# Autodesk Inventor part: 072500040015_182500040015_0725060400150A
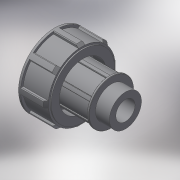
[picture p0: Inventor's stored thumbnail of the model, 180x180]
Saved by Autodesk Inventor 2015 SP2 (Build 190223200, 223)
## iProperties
Created: 2017-04
Part Number: 072500040015_182500040015_0725060400150A
Material: Generic
Description: PLASSON THREADED ADAPTOR 40-1.1/2"
Document SubType Name: Modeling
Designer: KIM
Density: 1 g/cm^3
Appearance: Default
Author: KIM
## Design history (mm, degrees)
derived "07250.ipt"
feature "Solid1::07250.ipt"
tag "TaggingFeature1"
body "Solid1"
other parameters: "d1" = 47.803, "d3" = 22, "d6" = 82, "d7" = 76.26, "d8" = 65.6, "d10" = 57.3636, "d12" = 28.6818, "d13" = 33.4621, "d14" = 25.3, "d15" = 61.5, "d16" = 3, "d18" = 22, "d19" = 26.4, "d24" = 9.5606, "d25" = 4.7803, "d27" = 0, "d28" = 3.82424, "d31" = 0.95606, "d35" = 360 deg, "d41" = 29.337, "d56" = 44, "d57" = 4, "d58" = 2, "d60" = 0, "d61" = 0.47803, "d64" = 0.47803, "d68" = 360 deg, "R_" = 47.803, "E_" = 82, "l_2" = 22
